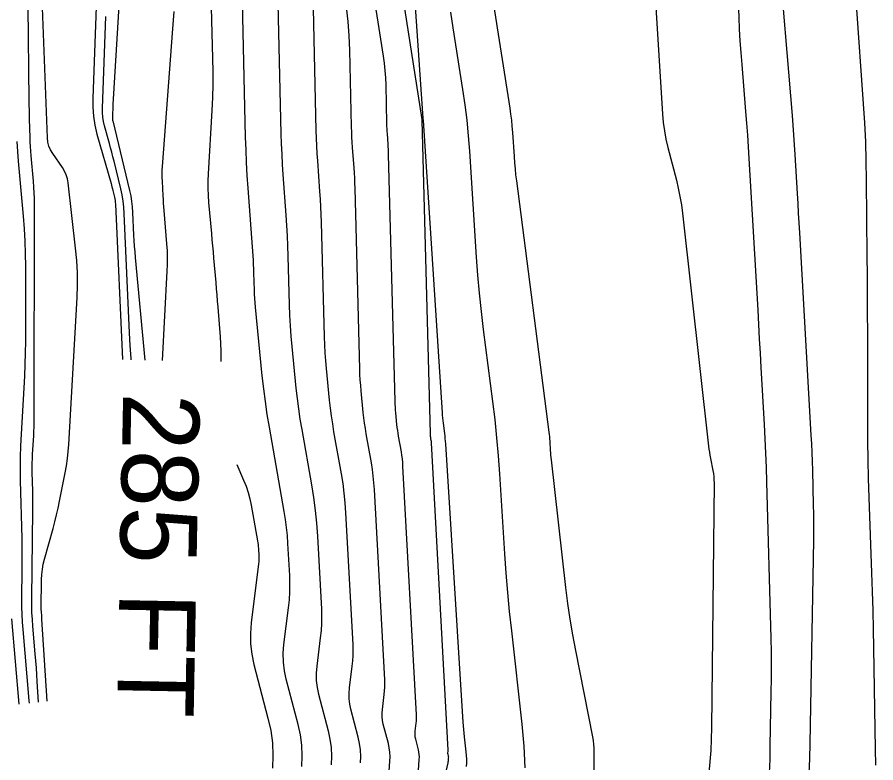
# Model space of a CAD drawing. Extents: x 1768942 to 1774819, y 723037 to 732099.
# Drawn here: x 1770861.8 to 1770929, y 724240.1 to 724298.6 of the extents above; entities that cross this region are included whole.
import ezdxf

# ---------------------------------------------------------------- set-up
doc = ezdxf.new("R2010")
doc.units = 0
doc.layers.add('R_Contour Annot', color=7, linetype='Continuous')
doc.layers.add('R_Contours', color=7, linetype='Continuous')

msp = doc.modelspace()

# ---------------------------------------------------------------- linework, layer by layer
at = {"layer": 'R_Contours'}
for points in [[(1770890.727, 724219.308), (1770895.532, 724240.143), (1770895.542, 724240.189), (1770895.55, 724240.235), (1770895.556, 724240.282), (1770895.56, 724240.328), (1770895.576, 724240.543), (1770895.577, 724240.576), (1770895.576, 724240.608), (1770895.571, 724240.64), (1770895.564, 724240.672), (1770895.528, 724240.81), (1770895.523, 724240.836), (1770895.52, 724240.863), (1770895.519, 724240.889), (1770895.521, 724240.916), (1770895.535, 724241.024), (1770895.537, 724241.051), (1770895.539, 724241.078), (1770895.539, 724241.105), (1770895.538, 724241.132), (1770894.234, 724265.228), (1770894.231, 724265.269), (1770894.227, 724265.309), (1770894.222, 724265.349), (1770894.215, 724265.389), (1770894.184, 724265.565), (1770894.179, 724265.597), (1770894.174, 724265.63), (1770894.17, 724265.662), (1770894.166, 724265.695), (1770894.153, 724265.826), (1770894.15, 724265.859), (1770894.148, 724265.892), (1770894.146, 724265.925), (1770894.145, 724265.957), (1770893.505, 724290.48), (1770893.505, 724290.49), (1770893.504, 724290.506), (1770893.503, 724290.544), (1770893.503, 724290.551), (1770893.502, 724290.558), (1770893.501, 724290.565), (1770893.5, 724290.571), (1770889.736, 724314.665)], [(1770891.917, 724314.606), (1770893.558, 724290.655), (1770893.559, 724290.64), (1770893.561, 724290.626), (1770893.563, 724290.612), (1770893.565, 724290.597), (1770893.574, 724290.54), (1770893.576, 724290.526), (1770893.577, 724290.512), (1770893.579, 724290.498), (1770893.58, 724290.483), (1770895.058, 724267.581), (1770895.073, 724267.377), (1770895.091, 724267.173), (1770895.112, 724266.969), (1770895.137, 724266.766), (1770895.242, 724265.954), (1770895.266, 724265.751), (1770895.287, 724265.547), (1770895.305, 724265.344), (1770895.32, 724265.139), (1770896.698, 724243.334), (1770896.718, 724243.043), (1770896.742, 724242.752), (1770896.769, 724242.462), (1770896.8, 724242.171), (1770896.931, 724241.011), (1770896.957, 724240.721), (1770896.969, 724240.43), (1770896.967, 724240.14), (1770896.952, 724239.849)], [(1770893.183, 724239.129), (1770893.277, 724240.405), (1770893.284, 724240.598), (1770893.274, 724240.789), (1770893.249, 724240.98), (1770893.207, 724241.168), (1770892.994, 724241.985), (1770892.96, 724242.141), (1770892.942, 724242.298), (1770892.94, 724242.456), (1770892.952, 724242.615), (1770893.032, 724243.253), (1770893.048, 724243.413), (1770893.058, 724243.573), (1770893.06, 724243.733), (1770893.055, 724243.893), (1770891.998, 724263.4), (1770891.979, 724263.682), (1770891.951, 724263.963), (1770891.914, 724264.243), (1770891.869, 724264.522), (1770891.654, 724265.742), (1770891.617, 724265.968), (1770891.583, 724266.194), (1770891.554, 724266.422), (1770891.529, 724266.649), (1770891.438, 724267.562), (1770891.417, 724267.79), (1770891.401, 724268.019), (1770891.388, 724268.248), (1770891.38, 724268.477), (1770890.876, 724287.824), (1770890.869, 724288.026), (1770890.86, 724288.228), (1770890.849, 724288.429), (1770890.836, 724288.631), (1770890.777, 724289.436), (1770890.763, 724289.638), (1770890.752, 724289.839), (1770890.744, 724290.041), (1770890.738, 724290.243), (1770890.668, 724293.266), (1770890.645, 724293.836), (1770890.604, 724294.405), (1770890.544, 724294.972), (1770890.465, 724295.537), (1770887.733, 724313.02)], [(1770920.712, 724239.354), (1770920.746, 724240.408), (1770920.771, 724241.462), (1770920.849, 724245.678), (1770920.862, 724246.732), (1770920.864, 724247.786), (1770920.854, 724248.841), (1770920.832, 724249.894), (1770920.506, 724262.161), (1770920.472, 724263.283), (1770920.43, 724264.404), (1770920.379, 724265.525), (1770920.319, 724266.645), (1770920.063, 724271.127), (1770919.999, 724272.247), (1770919.935, 724273.368), (1770919.871, 724274.488), (1770919.807, 724275.609), (1770919.124, 724287.498), (1770919.068, 724288.422), (1770919.006, 724289.346), (1770918.938, 724290.269), (1770918.863, 724291.192), (1770918.554, 724294.882), (1770918.481, 724295.805), (1770918.418, 724296.729), (1770918.364, 724297.653), (1770918.32, 724298.578), (1770917.732, 724312.387)], [(1770868.417, 724311.592), (1770867.693, 724292.234), (1770867.694, 724291.52), (1770867.751, 724290.812), (1770867.863, 724290.111), (1770868.031, 724289.417), (1770869.129, 724285.536), (1770869.166, 724285.404), (1770869.201, 724285.272), (1770869.236, 724285.139), (1770869.268, 724285.006), (1770869.397, 724284.474), (1770869.426, 724284.34), (1770869.448, 724284.206), (1770869.464, 724284.07), (1770869.473, 724283.934), (1770870.02, 724271.741)], [(1770870.465, 724311.536), (1770869.299, 724292.158), (1770869.292, 724292.021), (1770869.285, 724291.883), (1770869.28, 724291.745), (1770869.276, 724291.607), (1770869.257, 724290.818), (1770869.256, 724290.799), (1770869.255, 724290.78), (1770869.254, 724290.761), (1770869.253, 724290.742), (1770869.247, 724290.664), (1770869.246, 724290.647), (1770869.246, 724290.629), (1770869.246, 724290.612), (1770869.246, 724290.595), (1770869.25, 724290.525), (1770869.252, 724290.508), (1770869.254, 724290.49), (1770869.257, 724290.473), (1770869.26, 724290.456), (1770870.577, 724285.002), (1770870.67, 724284.573), (1770870.742, 724284.141), (1770870.793, 724283.705), (1770870.823, 724283.267), (1770870.902, 724281.508), (1770870.924, 724281.068), (1770870.952, 724280.629), (1770870.984, 724280.19), (1770871.023, 724279.751), (1770871.77, 724271.708)], [(1770884.083, 724239.851), (1770884.11, 724240.686), (1770884.069, 724241.514), (1770883.959, 724242.336), (1770883.78, 724243.152), (1770882.855, 724246.684), (1770882.711, 724247.359), (1770882.634, 724248.038), (1770882.622, 724248.722), (1770882.675, 724249.41), (1770883.037, 724252.299), (1770883.102, 724252.925), (1770883.138, 724253.552), (1770883.146, 724254.18), (1770883.126, 724254.809), (1770882.989, 724257.327), (1770882.946, 724257.956), (1770882.884, 724258.582), (1770882.802, 724259.206), (1770882.702, 724259.828), (1770881.535, 724266.449), (1770881.368, 724267.45), (1770881.22, 724268.453), (1770881.091, 724269.459), (1770880.98, 724270.467), (1770880.441, 724275.86), (1770880.411, 724276.193), (1770880.387, 724276.526), (1770880.369, 724276.86), (1770880.357, 724277.194), (1770880.322, 724278.532), (1770880.311, 724278.866), (1770880.297, 724279.2), (1770880.278, 724279.534), (1770880.256, 724279.867), (1770879.866, 724285.185), (1770879.8, 724286.183), (1770879.745, 724287.181), (1770879.704, 724288.18), (1770879.674, 724289.179), (1770879.211, 724309.203)], [(1770897.733, 724308.212), (1770900.363, 724291.453), (1770900.432, 724290.98), (1770900.489, 724290.507), (1770900.536, 724290.032), (1770900.573, 724289.556), (1770900.696, 724287.65), (1770900.73, 724287.173), (1770900.772, 724286.698), (1770900.822, 724286.223), (1770900.879, 724285.749), (1770903.421, 724266.068), (1770903.443, 724265.886), (1770903.462, 724265.704), (1770903.478, 724265.522), (1770903.491, 724265.339), (1770903.537, 724264.608), (1770903.55, 724264.426), (1770903.565, 724264.243), (1770903.582, 724264.061), (1770903.601, 724263.879), (1770904.732, 724253.87), (1770904.885, 724252.631), (1770905.063, 724251.395), (1770905.268, 724250.164), (1770905.498, 724248.937), (1770906.839, 724242.184), (1770906.89, 724241.885), (1770906.926, 724241.584), (1770906.946, 724241.281), (1770906.951, 724240.977), (1770906.936, 724239.521)], [(1770876.795, 724306.397), (1770877.086, 724295.347), (1770877.103, 724294.33), (1770877.098, 724293.312), (1770877.071, 724292.295), (1770877.024, 724291.279), (1770876.739, 724286.313), (1770876.717, 724285.747), (1770876.715, 724285.181), (1770876.734, 724284.615), (1770876.774, 724284.05), (1770876.99, 724281.619), (1770877.033, 724281.139), (1770877.075, 724280.658), (1770877.118, 724280.178), (1770877.16, 724279.698), (1770877.328, 724277.777), (1770877.369, 724277.296), (1770877.41, 724276.816), (1770877.451, 724276.335), (1770877.49, 724275.855), (1770877.681, 724273.532), (1770877.717, 724272.984), (1770877.734, 724272.436), (1770877.732, 724271.888), (1770877.721, 724271.595)], [(1770911.44, 724305.234), (1770912.328, 724290.97), (1770912.385, 724290.314), (1770912.473, 724289.662), (1770912.593, 724289.016), (1770912.743, 724288.375), (1770913.409, 724285.819), (1770913.563, 724285.178), (1770913.695, 724284.533), (1770913.803, 724283.883), (1770913.888, 724283.229), (1770915.931, 724264.969), (1770915.961, 724264.727), (1770915.995, 724264.485), (1770916.035, 724264.244), (1770916.08, 724264.004), (1770916.27, 724263.046), (1770916.312, 724262.806), (1770916.341, 724262.565), (1770916.357, 724262.322), (1770916.361, 724262.078), (1770916.164, 724242.883), (1770916.101, 724241.118), (1770915.95, 724239.363)], [(1770882.098, 724304.229), (1770882.44, 724289.445), (1770882.464, 724288.645), (1770882.497, 724287.846), (1770882.541, 724287.046), (1770882.594, 724286.248), (1770882.828, 724283.054), (1770882.882, 724282.255), (1770882.926, 724281.456), (1770882.961, 724280.657), (1770882.986, 724279.857), (1770883.086, 724276.035), (1770883.115, 724275.217), (1770883.159, 724274.401), (1770883.218, 724273.585), (1770883.292, 724272.77), (1770883.618, 724269.513), (1770883.707, 724268.7), (1770883.811, 724267.889), (1770883.93, 724267.079), (1770884.065, 724266.272), (1770884.832, 724261.919), (1770884.993, 724260.924), (1770885.123, 724259.924), (1770885.222, 724258.921), (1770885.292, 724257.915), (1770885.603, 724252.177), (1770885.621, 724251.617), (1770885.613, 724251.057), (1770885.581, 724250.498), (1770885.524, 724249.941), (1770885.244, 724247.711), (1770885.201, 724247.155), (1770885.211, 724246.603), (1770885.274, 724246.054), (1770885.39, 724245.509), (1770886.137, 724242.656), (1770886.281, 724241.997), (1770886.37, 724241.333), (1770886.404, 724240.664), (1770886.381, 724239.989)], [(1770921.364, 724304.17), (1770922.479, 724290.881), (1770922.54, 724290.116), (1770922.597, 724289.35), (1770922.649, 724288.584), (1770922.695, 724287.817), (1770922.871, 724284.75), (1770922.915, 724283.984), (1770922.959, 724283.217), (1770923.003, 724282.45), (1770923.047, 724281.683), (1770923.952, 724265.821), (1770923.988, 724265.136), (1770924.02, 724264.451), (1770924.046, 724263.766), (1770924.066, 724263.081), (1770924.139, 724260.34), (1770924.153, 724259.655), (1770924.16, 724258.969), (1770924.159, 724258.284), (1770924.15, 724257.599), (1770923.855, 724241.665), (1770923.828, 724240.484), (1770923.79, 724239.304)], [(1770864.122, 724244.97), (1770863.722, 724251.405), (1770863.717, 724251.473), (1770863.712, 724251.541), (1770863.707, 724251.61), (1770863.701, 724251.678), (1770863.678, 724251.951), (1770863.673, 724252.019), (1770863.669, 724252.088), (1770863.668, 724252.156), (1770863.668, 724252.225), (1770863.695, 724254.511), (1770863.713, 724254.913), (1770863.757, 724255.311), (1770863.826, 724255.706), (1770863.921, 724256.097), (1770864.587, 724258.502), (1770864.729, 724259.034), (1770864.861, 724259.568), (1770864.983, 724260.105), (1770865.095, 724260.644), (1770865.534, 724262.872), (1770865.633, 724263.424), (1770865.713, 724263.979), (1770865.774, 724264.537), (1770865.815, 724265.097), (1770866.466, 724276.623), (1770866.5, 724277.589), (1770866.493, 724278.554), (1770866.446, 724279.518), (1770866.357, 724280.48), (1770865.78, 724285.588), (1770865.723, 724285.913), (1770865.629, 724286.223), (1770865.496, 724286.519), (1770865.324, 724286.801), (1770864.563, 724287.9), (1770864.395, 724288.182), (1770864.272, 724288.479), (1770864.192, 724288.79), (1770864.158, 724289.117), (1770863.721, 724300.7)], [(1770862.624, 724299.436), (1770862.697, 724292.03), (1770862.701, 724291.67), (1770862.707, 724291.31), (1770862.715, 724290.951), (1770862.724, 724290.591), (1770862.764, 724289.152), (1770862.777, 724288.792), (1770862.795, 724288.433), (1770862.819, 724288.074), (1770862.848, 724287.715), (1770863.026, 724285.718), (1770863.061, 724285.265), (1770863.086, 724284.812), (1770863.101, 724284.358), (1770863.106, 724283.904), (1770863.092, 724267.175), (1770863.089, 724266.82), (1770863.081, 724266.465), (1770863.067, 724266.111), (1770863.048, 724265.756), (1770862.962, 724264.339), (1770862.944, 724263.985), (1770862.934, 724263.63), (1770862.931, 724263.276), (1770862.937, 724262.921), (1770862.974, 724261.421), (1770862.982, 724261.053), (1770862.986, 724260.685), (1770862.987, 724260.316), (1770862.984, 724259.948), (1770862.9, 724253.017), (1770862.9, 724252.473), (1770862.914, 724251.929), (1770862.941, 724251.386), (1770862.98, 724250.844), (1770863.167, 724248.675), (1770863.212, 724248.132), (1770863.254, 724247.59), (1770863.292, 724247.047), (1770863.328, 724246.504), (1770863.428, 724244.894)], [(1770890.807, 724237.93), (1770890.979, 724240.266), (1770890.99, 724240.62), (1770890.973, 724240.971), (1770890.926, 724241.319), (1770890.851, 724241.664), (1770890.459, 724243.16), (1770890.398, 724243.445), (1770890.365, 724243.733), (1770890.36, 724244.022), (1770890.383, 724244.313), (1770890.529, 724245.482), (1770890.559, 724245.775), (1770890.576, 724246.067), (1770890.58, 724246.361), (1770890.571, 724246.654), (1770889.763, 724261.572), (1770889.727, 724262.095), (1770889.675, 724262.617), (1770889.607, 724263.136), (1770889.524, 724263.654), (1770889.124, 724265.919), (1770889.055, 724266.338), (1770888.992, 724266.759), (1770888.938, 724267.181), (1770888.892, 724267.604), (1770888.722, 724269.298), (1770888.684, 724269.722), (1770888.653, 724270.146), (1770888.631, 724270.571), (1770888.616, 724270.996), (1770888.246, 724285.169), (1770888.233, 724285.57), (1770888.216, 724285.971), (1770888.193, 724286.371), (1770888.166, 724286.772), (1770888.049, 724288.374), (1770888.022, 724288.774), (1770888, 724289.175), (1770887.984, 724289.576), (1770887.972, 724289.977), (1770887.833, 724295.988), (1770887.788, 724297.121), (1770887.706, 724298.252), (1770887.586, 724299.379)], [(1770929.034, 724239.954), (1770929.011, 724241.214), (1770928.886, 724249.137), (1770928.859, 724250.613), (1770928.824, 724252.088), (1770928.781, 724253.564), (1770928.729, 724255.039), (1770928.507, 724260.939), (1770928.459, 724262.414), (1770928.424, 724263.89), (1770928.403, 724265.366), (1770928.396, 724266.842), (1770928.396, 724273.88), (1770928.394, 724275.372), (1770928.389, 724276.865), (1770928.38, 724278.357), (1770928.368, 724279.85), (1770928.313, 724285.82), (1770928.288, 724287.312), (1770928.239, 724288.804), (1770928.166, 724290.294), (1770928.07, 724291.783), (1770927.508, 724299.571)], [(1770870.707, 724271.728), (1770870.699, 724271.842), (1770870.636, 724272.836), (1770870.586, 724273.831), (1770870.166, 724283.197), (1770870.133, 724283.685), (1770870.076, 724284.17), (1770869.995, 724284.652), (1770869.892, 724285.131), (1770869.369, 724287.299), (1770869.283, 724287.646), (1770869.194, 724287.991), (1770869.102, 724288.336), (1770869.007, 724288.68), (1770868.618, 724290.053), (1770868.535, 724290.398), (1770868.479, 724290.746), (1770868.451, 724291.098), (1770868.45, 724291.453), (1770868.719, 724298.642)], [(1770874.039, 724299.016), (1770874.001, 724298.348), (1770873.955, 724297.68), (1770873.136, 724286.868), (1770873.12, 724286.582), (1770873.112, 724286.296), (1770873.114, 724286.01), (1770873.125, 724285.724), (1770873.189, 724284.579), (1770873.206, 724284.292), (1770873.225, 724284.006), (1770873.246, 724283.72), (1770873.268, 724283.434), (1770873.484, 724280.809), (1770873.518, 724280.276), (1770873.535, 724279.743), (1770873.533, 724279.209), (1770873.514, 724278.676), (1770873.137, 724271.682)], [(1770888.68, 724240.128), (1770888.697, 724240.642), (1770888.672, 724241.152), (1770888.604, 724241.658), (1770888.494, 724242.16), (1770887.924, 724244.334), (1770887.836, 724244.75), (1770887.788, 724245.168), (1770887.781, 724245.589), (1770887.814, 724246.012), (1770888.027, 724247.711), (1770888.07, 724248.136), (1770888.095, 724248.562), (1770888.1, 724248.989), (1770888.087, 724249.416), (1770887.527, 724259.743), (1770887.475, 724260.508), (1770887.399, 724261.27), (1770887.3, 724262.03), (1770887.178, 724262.787), (1770886.595, 724266.095), (1770886.492, 724266.709), (1770886.402, 724267.324), (1770886.322, 724267.94), (1770886.255, 724268.558), (1770886.007, 724271.034), (1770885.951, 724271.653), (1770885.906, 724272.273), (1770885.873, 724272.894), (1770885.851, 724273.516), (1770885.616, 724282.513), (1770885.597, 724283.113), (1770885.571, 724283.714), (1770885.537, 724284.313), (1770885.497, 724284.913), (1770885.322, 724287.311), (1770885.281, 724287.91), (1770885.249, 724288.51), (1770885.224, 724289.111), (1770885.206, 724289.711), (1770884.985, 724299.256)], [(1770895.731, 724298.967), (1770895.907, 724297.758), (1770896.665, 724292.926), (1770896.841, 724291.717), (1770896.989, 724290.504), (1770897.109, 724289.289), (1770897.202, 724288.07), (1770897.737, 724279.779), (1770897.84, 724278.358), (1770897.966, 724276.939), (1770898.115, 724275.522), (1770898.286, 724274.107), (1770899.016, 724268.453), (1770899.187, 724267.039), (1770899.335, 724265.622), (1770899.459, 724264.203), (1770899.561, 724262.782), (1770899.956, 724256.53), (1770900.061, 724255.014), (1770900.185, 724253.501), (1770900.327, 724251.988), (1770900.488, 724250.478), (1770901.313, 724243.178), (1770901.466, 724241.457), (1770901.538, 724239.735)], [(1770861.754, 724288.834), (1770861.805, 724288.06), (1770861.868, 724287.286), (1770862.252, 724282.976), (1770862.328, 724282), (1770862.383, 724281.022), (1770862.415, 724280.043), (1770862.425, 724279.064), (1770862.42, 724273.17), (1770862.412, 724272.261), (1770862.391, 724271.352), (1770862.356, 724270.444), (1770862.308, 724269.536), (1770862.086, 724265.905), (1770862.041, 724264.997), (1770862.015, 724264.088), (1770862.008, 724263.18), (1770862.021, 724262.271), (1770862.136, 724257.732), (1770862.148, 724257.136), (1770862.155, 724256.54), (1770862.156, 724255.944), (1770862.152, 724255.347), (1770862.123, 724252.962), (1770862.123, 724252.366), (1770862.138, 724251.77), (1770862.167, 724251.175), (1770862.211, 724250.581), (1770862.687, 724245.035), (1770862.706, 724244.814)], [(1770878.977, 724263.52), (1770879.514, 724262.306), (1770879.709, 724261.824), (1770879.875, 724261.333), (1770880.011, 724260.833), (1770880.116, 724260.324), (1770880.608, 724257.537), (1770880.631, 724257.389), (1770880.651, 724257.241), (1770880.666, 724257.092), (1770880.676, 724256.943), (1770880.708, 724256.344), (1770880.713, 724256.194), (1770880.711, 724256.045), (1770880.703, 724255.896), (1770880.687, 724255.747), (1770880.106, 724251.108), (1770880.042, 724250.288), (1770880.057, 724249.473), (1770880.149, 724248.663), (1770880.32, 724247.859), (1770881.424, 724243.648), (1770881.636, 724242.676), (1770881.768, 724241.695), (1770881.817, 724240.707), (1770881.784, 724239.712)], [(1770861.346, 724251.414), (1770861.921, 724244.728)]]:
    msp.add_lwpolyline(points, dxfattribs=at)

# ---------------------------------------------------------------- texts
at = {"layer": 'R_Contour Annot'}
msp.add_text('285 FT', height=6, rotation=268.91655, dxfattribs=at).set_placement((1770870.082, 724269.164))

doc.saveas('drawing.dxf')
